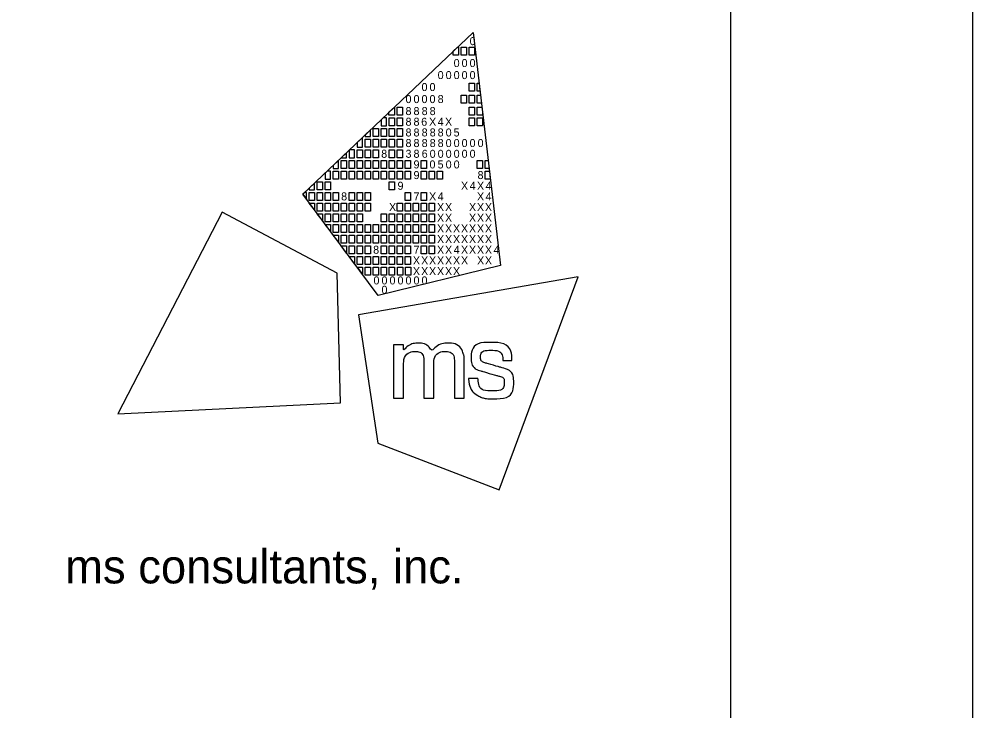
# Model space of a CAD drawing. Extents: x 0 to 34, y 0 to 22.
# Drawn here: x 32.032 to 34, y 2.686 to 4.114 of the extents above; entities that cross this region are included whole.
import ezdxf

# ---------------------------------------------------------------- set-up
doc = ezdxf.new("R2010")
doc.units = 0
for name, color, linetype in [('SH_Border', 7, 'Continuous'), ('SH_Cut_Line', 7, 'Continuous'), ('SH_Data', 7, 'Continuous')]:
    doc.layers.add(name, color=color, linetype=linetype)

msp = doc.modelspace()

# ---------------------------------------------------------------- linework, layer by layer
at = {"layer": 'SH_Border'}
for p, q in [((32.6175, 3.7519), (32.9688, 4.0861)), ((32.9688, 4.0861), (32.9688, 4.0861)), ((32.9688, 4.0861), (33.0253, 3.6052)), ((32.773, 3.543), (32.6175, 3.7519)), ((33.0253, 3.6052), (32.773, 3.543))]:
    msp.add_line(p, q, dxfattribs=at)
for points in [[(1.5, 21.5), (33.5, 21.5), (33.5, 0.5), (1.5, 0.5)], [(32.9279, 4.0472), (32.9369, 4.0558), (32.9389, 4.0558), (32.9389, 4.0393), (32.9279, 4.0393)], [(32.9444, 4.0558), (32.9554, 4.0558), (32.9554, 4.0393), (32.9444, 4.0393)], [(32.9609, 4.0558), (32.9719, 4.0558), (32.9719, 4.0393), (32.9609, 4.0393)], [(32.9606, 3.9815), (32.9716, 3.9815), (32.9716, 3.965), (32.9606, 3.965)], [(32.9771, 3.9815), (32.9811, 3.9815), (32.983, 3.965), (32.9771, 3.965)], [(32.9441, 3.9567), (32.9551, 3.9567), (32.9551, 3.9402), (32.9441, 3.9402)], [(32.9606, 3.9567), (32.9716, 3.9567), (32.9716, 3.9402), (32.9606, 3.9402)], [(32.9771, 3.9567), (32.984, 3.9567), (32.9859, 3.9402), (32.9771, 3.9402)], [(32.7953, 3.9211), (32.8064, 3.9316), (32.8064, 3.9154), (32.7953, 3.9154)], [(32.8123, 3.9319), (32.8233, 3.9319), (32.8233, 3.9154), (32.8123, 3.9154)], [(32.9606, 3.9319), (32.9716, 3.9319), (32.9716, 3.9154), (32.9606, 3.9154)], [(32.9771, 3.9319), (32.9869, 3.9319), (32.9881, 3.9218), (32.9881, 3.9154), (32.9771, 3.9154)], [(32.7958, 3.9099), (32.8068, 3.9099), (32.8068, 3.8934), (32.7958, 3.8934)], [(32.8123, 3.9099), (32.8233, 3.9099), (32.8233, 3.8934), (32.8123, 3.8934)], [(32.9606, 3.9099), (32.9716, 3.9099), (32.9716, 3.8934), (32.9606, 3.8934)], [(32.9771, 3.9099), (32.9881, 3.9099), (32.9881, 3.8934), (32.9771, 3.8934)], [(32.7627, 3.8879), (32.7737, 3.8879), (32.7737, 3.8714), (32.7627, 3.8714)], [(32.7793, 3.8879), (32.7903, 3.8879), (32.7903, 3.8714), (32.7793, 3.8714)], [(32.7958, 3.8879), (32.8068, 3.8879), (32.8068, 3.8714), (32.7958, 3.8714)], [(32.8123, 3.8879), (32.8233, 3.8879), (32.8233, 3.8714), (32.8123, 3.8714)], [(32.7462, 3.8659), (32.7572, 3.8659), (32.7572, 3.8494), (32.7462, 3.8494)], [(32.7627, 3.8659), (32.7737, 3.8659), (32.7737, 3.8494), (32.7627, 3.8494)], [(32.7793, 3.8659), (32.7903, 3.8659), (32.7903, 3.8494), (32.7793, 3.8494)], [(32.7958, 3.8659), (32.8068, 3.8659), (32.8068, 3.8494), (32.7958, 3.8494)], [(32.8123, 3.8659), (32.8233, 3.8659), (32.8233, 3.8494), (32.8123, 3.8494)], [(32.7297, 3.8439), (32.7407, 3.8439), (32.7407, 3.8273), (32.7297, 3.8273)], [(32.7462, 3.8439), (32.7572, 3.8439), (32.7572, 3.8273), (32.7462, 3.8273)], [(32.7627, 3.8439), (32.7737, 3.8439), (32.7737, 3.8273), (32.7627, 3.8273)], [(32.7958, 3.8439), (32.8068, 3.8439), (32.8068, 3.8273), (32.7958, 3.8273)], [(32.8123, 3.8439), (32.8233, 3.8439), (32.8233, 3.8273), (32.8123, 3.8273)], [(32.6967, 3.8218), (32.7077, 3.8218), (32.7077, 3.8053), (32.6967, 3.8053)], [(32.7132, 3.8218), (32.7242, 3.8218), (32.7242, 3.8053), (32.7132, 3.8053)], [(32.7297, 3.8218), (32.7407, 3.8218), (32.7407, 3.8053), (32.7297, 3.8053)], [(32.7462, 3.8218), (32.7572, 3.8218), (32.7572, 3.8053), (32.7462, 3.8053)], [(32.7627, 3.8218), (32.7737, 3.8218), (32.7737, 3.8053), (32.7627, 3.8053)], [(32.7793, 3.8218), (32.7903, 3.8218), (32.7903, 3.8053), (32.7793, 3.8053)], [(32.7958, 3.8218), (32.8068, 3.8218), (32.8068, 3.8053), (32.7958, 3.8053)], [(32.8123, 3.8218), (32.8233, 3.8218), (32.8233, 3.8053), (32.8123, 3.8053)], [(32.8288, 3.8218), (32.8398, 3.8218), (32.8398, 3.8053), (32.8288, 3.8053)], [(32.8618, 3.8218), (32.8728, 3.8218), (32.8728, 3.8053), (32.8618, 3.8053)], [(32.9771, 3.8218), (32.9881, 3.8218), (32.9881, 3.8053), (32.9771, 3.8053)], [(32.9935, 3.8218), (32.9998, 3.8218), (33.0018, 3.8053), (32.9935, 3.8053)], [(32.6802, 3.7998), (32.6912, 3.7998), (32.6912, 3.7833), (32.6802, 3.7833)], [(32.6967, 3.7998), (32.7077, 3.7998), (32.7077, 3.7833), (32.6967, 3.7833)], [(32.7132, 3.7998), (32.7242, 3.7998), (32.7242, 3.7833), (32.7132, 3.7833)], [(32.7297, 3.7998), (32.7407, 3.7998), (32.7407, 3.7833), (32.7297, 3.7833)], [(32.7462, 3.7998), (32.7572, 3.7998), (32.7572, 3.7833), (32.7462, 3.7833)], [(32.7627, 3.7998), (32.7737, 3.7998), (32.7737, 3.7833), (32.7627, 3.7833)], [(32.7793, 3.7998), (32.7903, 3.7998), (32.7903, 3.7833), (32.7793, 3.7833)], [(32.7958, 3.7998), (32.8068, 3.7998), (32.8068, 3.7833), (32.7958, 3.7833)], [(32.8123, 3.7998), (32.8233, 3.7998), (32.8233, 3.7833), (32.8123, 3.7833)], [(32.8288, 3.7998), (32.8398, 3.7998), (32.8398, 3.7833), (32.8288, 3.7833)], [(32.8618, 3.7998), (32.8728, 3.7998), (32.8728, 3.7833), (32.8618, 3.7833)], [(32.8783, 3.7998), (32.8893, 3.7998), (32.8893, 3.7833), (32.8783, 3.7833)], [(32.8947, 3.7998), (32.9057, 3.7998), (32.9057, 3.7833), (32.8947, 3.7833)], [(32.9935, 3.7998), (33.0024, 3.7998), (33.0044, 3.7833), (32.9935, 3.7833)], [(32.6471, 3.7778), (32.6581, 3.7778), (32.6581, 3.7613), (32.6471, 3.7613)], [(32.6637, 3.7778), (32.6747, 3.7778), (32.6747, 3.7613), (32.6637, 3.7613)], [(32.7958, 3.7778), (32.8068, 3.7778), (32.8068, 3.7613), (32.7958, 3.7613)], [(32.6306, 3.7558), (32.6416, 3.7558), (32.6416, 3.7393), (32.6306, 3.7393)], [(32.6471, 3.7558), (32.6581, 3.7558), (32.6581, 3.7393), (32.6471, 3.7393)], [(32.6637, 3.7558), (32.6747, 3.7558), (32.6747, 3.7393), (32.6637, 3.7393)], [(32.6802, 3.7558), (32.6912, 3.7558), (32.6912, 3.7393), (32.6802, 3.7393)], [(32.7132, 3.7558), (32.7242, 3.7558), (32.7242, 3.7393), (32.7132, 3.7393)], [(32.7297, 3.7558), (32.7407, 3.7558), (32.7407, 3.7393), (32.7297, 3.7393)], [(32.7462, 3.7558), (32.7572, 3.7558), (32.7572, 3.7393), (32.7462, 3.7393)], [(32.8288, 3.7558), (32.8398, 3.7558), (32.8398, 3.7393), (32.8288, 3.7393)], [(32.8618, 3.7558), (32.8728, 3.7558), (32.8728, 3.7393), (32.8618, 3.7393)], [(32.6306, 3.7338), (32.6416, 3.7338), (32.6416, 3.72)], [(32.6471, 3.7338), (32.6581, 3.7338), (32.6581, 3.7173), (32.6471, 3.7173)], [(32.6637, 3.7338), (32.6747, 3.7338), (32.6747, 3.7173), (32.6637, 3.7173)], [(32.6802, 3.7338), (32.6912, 3.7338), (32.6912, 3.7173), (32.6802, 3.7173)], [(32.6967, 3.7338), (32.7077, 3.7338), (32.7077, 3.7173), (32.6967, 3.7173)], [(32.7132, 3.7338), (32.7242, 3.7338), (32.7242, 3.7173), (32.7132, 3.7173)], [(32.7297, 3.7338), (32.7407, 3.7338), (32.7407, 3.7173), (32.7297, 3.7173)], [(32.7462, 3.7338), (32.7572, 3.7338), (32.7572, 3.7173), (32.7462, 3.7173)], [(32.8123, 3.7338), (32.8233, 3.7338), (32.8233, 3.7173), (32.8123, 3.7173)], [(32.8288, 3.7338), (32.8398, 3.7338), (32.8398, 3.7173), (32.8288, 3.7173)], [(32.8453, 3.7338), (32.8563, 3.7338), (32.8563, 3.7173), (32.8453, 3.7173)], [(32.8618, 3.7338), (32.8728, 3.7338), (32.8728, 3.7173), (32.8618, 3.7173)], [(32.8783, 3.7338), (32.8893, 3.7338), (32.8893, 3.7173), (32.8783, 3.7173)], [(32.6471, 3.7117), (32.6581, 3.7117), (32.6581, 3.698)], [(32.6637, 3.7117), (32.6747, 3.7117), (32.6747, 3.6952), (32.6637, 3.6952)], [(32.6802, 3.7117), (32.6912, 3.7117), (32.6912, 3.6952), (32.6802, 3.6952)], [(32.6967, 3.7117), (32.7077, 3.7117), (32.7077, 3.6952), (32.6967, 3.6952)], [(32.7132, 3.7117), (32.7242, 3.7117), (32.7242, 3.6952), (32.7132, 3.6952)], [(32.7297, 3.7117), (32.7407, 3.7117), (32.7407, 3.6952), (32.7297, 3.6952)], [(32.7793, 3.7117), (32.7903, 3.7117), (32.7903, 3.6952), (32.7793, 3.6952)], [(32.7958, 3.7117), (32.8068, 3.7117), (32.8068, 3.6952), (32.7958, 3.6952)], [(32.8123, 3.7117), (32.8233, 3.7117), (32.8233, 3.6952), (32.8123, 3.6952)], [(32.8288, 3.7117), (32.8398, 3.7117), (32.8398, 3.6952), (32.8288, 3.6952)], [(32.8453, 3.7117), (32.8563, 3.7117), (32.8563, 3.6952), (32.8453, 3.6952)], [(32.8618, 3.7117), (32.8728, 3.7117), (32.8728, 3.6952), (32.8618, 3.6952)], [(32.8783, 3.7117), (32.8893, 3.7117), (32.8893, 3.6952), (32.8783, 3.6952)], [(32.6637, 3.6897), (32.6747, 3.6897), (32.6747, 3.676)], [(32.6747, 3.6897), (32.6747, 3.6897), (32.6747, 3.6897)], [(32.6802, 3.6897), (32.6912, 3.6897), (32.6912, 3.6732), (32.6802, 3.6732)], [(32.6967, 3.6897), (32.7077, 3.6897), (32.7077, 3.6732), (32.6967, 3.6732)], [(32.7132, 3.6897), (32.7242, 3.6897), (32.7242, 3.6732), (32.7132, 3.6732)], [(32.7297, 3.6897), (32.7407, 3.6897), (32.7407, 3.6732), (32.7297, 3.6732)], [(32.7462, 3.6897), (32.7572, 3.6897), (32.7572, 3.6732), (32.7462, 3.6732)], [(32.7627, 3.6897), (32.7737, 3.6897), (32.7737, 3.6732), (32.7627, 3.6732)], [(32.7793, 3.6897), (32.7903, 3.6897), (32.7903, 3.6732), (32.7793, 3.6732)], [(32.7958, 3.6897), (32.8068, 3.6897), (32.8068, 3.6732), (32.7958, 3.6732)], [(32.8123, 3.6897), (32.8233, 3.6897), (32.8233, 3.6732), (32.8123, 3.6732)], [(32.8288, 3.6897), (32.8398, 3.6897), (32.8398, 3.6732), (32.8288, 3.6732)], [(32.8453, 3.6897), (32.8563, 3.6897), (32.8563, 3.6732), (32.8453, 3.6732)], [(32.8618, 3.6897), (32.8728, 3.6897), (32.8728, 3.6732), (32.8618, 3.6732)], [(32.8783, 3.6897), (32.8893, 3.6897), (32.8893, 3.6732), (32.8783, 3.6732)], [(32.6802, 3.6677), (32.6912, 3.6677), (32.6912, 3.654)], [(32.6967, 3.6677), (32.7077, 3.6677), (32.7077, 3.6512), (32.6967, 3.6512)], [(32.7132, 3.6677), (32.7242, 3.6677), (32.7242, 3.6512), (32.7132, 3.6512)], [(32.7297, 3.6677), (32.7407, 3.6677), (32.7407, 3.6512), (32.7297, 3.6512)], [(32.7462, 3.6677), (32.7572, 3.6677), (32.7572, 3.6512), (32.7462, 3.6512)], [(32.7627, 3.6677), (32.7737, 3.6677), (32.7737, 3.6512), (32.7627, 3.6512)], [(32.7793, 3.6677), (32.7903, 3.6677), (32.7903, 3.6512), (32.7793, 3.6512)], [(32.7958, 3.6677), (32.8068, 3.6677), (32.8068, 3.6512), (32.7958, 3.6512)], [(32.8123, 3.6677), (32.8233, 3.6677), (32.8233, 3.6512), (32.8123, 3.6512)], [(32.8288, 3.6677), (32.8398, 3.6677), (32.8398, 3.6512), (32.8288, 3.6512)], [(32.8453, 3.6677), (32.8563, 3.6677), (32.8563, 3.6512), (32.8453, 3.6512)], [(32.8618, 3.6677), (32.8728, 3.6677), (32.8728, 3.6512), (32.8618, 3.6512)], [(32.8783, 3.6677), (32.8893, 3.6677), (32.8893, 3.6512), (32.8783, 3.6512)], [(32.7077, 3.6305), (32.6965, 3.6457), (32.7077, 3.6457)], [(32.7132, 3.6457), (32.7242, 3.6457), (32.7242, 3.6292), (32.7132, 3.6292)], [(32.7297, 3.6457), (32.7407, 3.6457), (32.7407, 3.6292), (32.7297, 3.6292)], [(32.7462, 3.6457), (32.7572, 3.6457), (32.7572, 3.6292), (32.7462, 3.6292)], [(32.7793, 3.6457), (32.7903, 3.6457), (32.7903, 3.6292), (32.7793, 3.6292)], [(32.7958, 3.6457), (32.8068, 3.6457), (32.8068, 3.6292), (32.7958, 3.6292)], [(32.8123, 3.6457), (32.8233, 3.6457), (32.8233, 3.6292), (32.8123, 3.6292)], [(32.8288, 3.6457), (32.8398, 3.6457), (32.8398, 3.6292), (32.8288, 3.6292)], [(32.8618, 3.6457), (32.8728, 3.6457), (32.8728, 3.6292), (32.8618, 3.6292)], [(32.8783, 3.6457), (32.8893, 3.6457), (32.8893, 3.6292), (32.8783, 3.6292)], [(32.724, 3.6082), (32.7132, 3.6237), (32.7242, 3.6237)], [(32.7297, 3.6237), (32.7407, 3.6237), (32.7407, 3.6072), (32.7297, 3.6072)], [(32.7462, 3.6237), (32.7572, 3.6237), (32.7572, 3.6072), (32.7462, 3.6072)], [(32.7627, 3.6237), (32.7737, 3.6237), (32.7737, 3.6072), (32.7627, 3.6072)], [(32.7793, 3.6237), (32.7903, 3.6237), (32.7903, 3.6072), (32.7793, 3.6072)], [(32.7958, 3.6237), (32.8068, 3.6237), (32.8068, 3.6072), (32.7958, 3.6072)], [(32.8123, 3.6237), (32.8233, 3.6237), (32.8233, 3.6072), (32.8123, 3.6072)], [(32.8288, 3.6237), (32.8398, 3.6237), (32.8398, 3.6072), (32.8288, 3.6072)], [(32.7302, 3.6017), (32.7407, 3.6017), (32.7408, 3.5875)], [(32.7463, 3.6017), (32.7573, 3.6017), (32.7573, 3.5852), (32.7463, 3.5852)], [(32.763, 3.6017), (32.774, 3.6017), (32.774, 3.5852), (32.763, 3.5852)], [(32.7794, 3.6017), (32.7904, 3.6017), (32.7904, 3.5852), (32.7794, 3.5852)], [(32.796, 3.6017), (32.807, 3.6017), (32.807, 3.5852), (32.796, 3.5852)], [(32.8129, 3.6017), (32.8239, 3.6017), (32.8239, 3.5851), (32.8129, 3.5851)], [(32.8296, 3.6017), (32.8406, 3.6017), (32.8406, 3.5851), (32.8296, 3.5851)]]:
    msp.add_lwpolyline(points, close=True, dxfattribs=at)
for points in [[(32.7903, 3.9099), (32.7836, 3.9099), (32.7793, 3.9058), (32.7793, 3.8934), (32.7903, 3.8934), (32.7903, 3.9099)], [(32.7572, 3.8849), (32.7462, 3.8744), (32.7462, 3.8714), (32.7572, 3.8714), (32.7572, 3.8849)], [(32.7407, 3.8691), (32.7297, 3.8587), (32.7297, 3.8494), (32.7407, 3.8494), (32.7407, 3.8691)], [(32.7077, 3.8377), (32.6968, 3.8273), (32.7077, 3.8273), (32.7077, 3.8377)], [(32.7242, 3.8439), (32.7141, 3.8439), (32.7132, 3.843), (32.7132, 3.8273), (32.7242, 3.8273), (32.7242, 3.8439)], [(32.6912, 3.822), (32.6802, 3.8115), (32.6802, 3.8053), (32.6912, 3.8053), (32.6912, 3.822)], [(32.6747, 3.7998), (32.6679, 3.7998), (32.6637, 3.7958), (32.6637, 3.7833), (32.6747, 3.7833), (32.6747, 3.7998)], [(32.6416, 3.7749), (32.6306, 3.7644), (32.6306, 3.7613), (32.6416, 3.7613), (32.6416, 3.7749)], [(32.6251, 3.7558), (32.6216, 3.7558), (32.6175, 3.7519), (32.6251, 3.7417), (32.6251, 3.7558)], [(32.4512, 3.7149), (32.2359, 3.2988), (32.6956, 3.3215), (32.6884, 3.5892), (32.4512, 3.7149)], [(33.0229, 3.1422), (33.1859, 3.5814), (32.7324, 3.5029), (32.7722, 3.2381), (33.0229, 3.1422)]]:
    msp.add_lwpolyline(points, dxfattribs=at)
for points in [[(32.8048, 3.3315), (32.8048, 3.3315), (32.8048, 3.4409), (32.8048, 3.4409), (32.8048, 3.4409), (32.8255, 3.4409), (32.8255, 3.4409), (32.8255, 3.4409), (32.8255, 3.4297), (32.8255, 3.4297), (32.8346, 3.4399), (32.8457, 3.4445), (32.8555, 3.4445), (32.8688, 3.4445), (32.8791, 3.4372), (32.8837, 3.4266), (32.8915, 3.4381), (32.905, 3.4446), (32.9166, 3.4446), (32.9325, 3.4446), (32.9451, 3.435), (32.9494, 3.4213), (32.9494, 3.4212), (32.9494, 3.4212), (32.9494, 3.4212), (32.9501, 3.419), (32.9506, 3.4172), (32.9506, 3.4071), (32.9506, 3.4071), (32.9506, 3.3314), (32.9506, 3.3314), (32.9506, 3.3314), (32.9303, 3.3314), (32.9303, 3.3314), (32.9303, 3.3314), (32.9303, 3.4048), (32.9303, 3.4048), (32.9303, 3.4201), (32.9219, 3.4274), (32.911, 3.4274), (32.8995, 3.4274), (32.8879, 3.4171), (32.8879, 3.4001), (32.8879, 3.4001), (32.8879, 3.3315), (32.8879, 3.3315), (32.8879, 3.3315), (32.8674, 3.3315), (32.8674, 3.3315), (32.8674, 3.3315), (32.8674, 3.4059), (32.8674, 3.4059), (32.8674, 3.4203), (32.8588, 3.4274), (32.8496, 3.4274), (32.8384, 3.4274), (32.8254, 3.417), (32.8254, 3.3962), (32.8254, 3.3962), (32.8254, 3.3315), (32.8254, 3.3315), (32.8254, 3.3315), (32.8048, 3.3315), (32.8048, 3.3315)], [(32.9595, 3.3709), (32.9595, 3.3709), (32.9595, 3.3717), (32.9595, 3.3717), (32.9595, 3.3717), (32.9603, 3.3717), (32.9603, 3.3717), (32.9603, 3.3717), (32.9783, 3.3717), (32.9783, 3.3717), (32.9783, 3.3717), (32.9789, 3.3717), (32.9789, 3.3717), (32.9789, 3.3717), (32.979, 3.371), (32.979, 3.371), (32.9803, 3.3554), (32.9887, 3.346), (33.009, 3.346), (33.0273, 3.346), (33.0333, 3.3554), (33.0333, 3.3631), (33.0333, 3.3732), (33.0256, 3.3758), (33.0175, 3.378), (33.0175, 3.378), (32.987, 3.3867), (32.987, 3.3867), (32.972, 3.3909), (32.9648, 3.4019), (32.9648, 3.4142), (32.9648, 3.4303), (32.9768, 3.4462), (33.0052, 3.4462), (33.0348, 3.4462), (33.0489, 3.4285), (33.0489, 3.4095), (33.0489, 3.4095), (33.0489, 3.4087), (33.0489, 3.4087), (33.0489, 3.4087), (33.0482, 3.4087), (33.0482, 3.4087), (33.0482, 3.4087), (33.0312, 3.4087), (33.0312, 3.4087), (33.0312, 3.4087), (33.0305, 3.4087), (33.0305, 3.4087), (33.0305, 3.4087), (33.0305, 3.4094), (33.0305, 3.4094), (33.0301, 3.4208), (33.0226, 3.43), (33.0056, 3.43), (32.9891, 3.43), (32.9843, 3.4218), (32.9843, 3.4157), (32.9843, 3.4108), (32.9869, 3.4059), (32.9959, 3.4033), (32.9959, 3.4033), (33.0255, 3.3948), (33.0255, 3.3948), (33.0462, 3.3889), (33.0527, 3.3777), (33.0527, 3.3639), (33.0527, 3.3462), (33.041, 3.3298), (33.0087, 3.3298), (32.9952, 3.3298), (32.9877, 3.3321), (32.9823, 3.3348), (32.969, 3.3414), (32.9609, 3.3536), (32.9595, 3.3709)]]:
    msp.add_open_spline(points, degree=3, dxfattribs=at)
at = {"layer": 'SH_Cut_Line'}
msp.add_lwpolyline([(0, 0), (34, 0), (34, 22), (0, 22)], close=True, dxfattribs=at)
at = {"layer": 'SH_Data'}
msp.add_line((32.75, 3.5), (32.75, 3.5), dxfattribs=at)

# ---------------------------------------------------------------- texts
at = {"layer": 'SH_Border'}
for s, height, p in [('0', 0.0165, (32.9617, 4.0597)), ('0', 0.0165, (32.9288, 4.0145)), ('0', 0.0165, (32.9452, 4.0145)), ('0', 0.0165, (32.9617, 4.0145)), ('0', 0.0165, (32.8958, 3.9897)), ('0', 0.0165, (32.9123, 3.9897)), ('0', 0.0165, (32.9288, 3.9897)), ('0', 0.0165, (32.9452, 3.9897)), ('0', 0.0165, (32.9617, 3.9897)), ('0', 0.0165, (32.8625, 3.965)), ('0', 0.0165, (32.879, 3.965)), ('0', 0.0165, (32.8295, 3.9402)), ('0', 0.0165, (32.846, 3.9402)), ('0', 0.0165, (32.8625, 3.9402)), ('0', 0.0165, (32.879, 3.9402)), ('8', 0.0165, (32.8958, 3.9402)), ('8', 0.0165, (32.8295, 3.9154)), ('8', 0.0165, (32.846, 3.9154)), ('8', 0.0165, (32.8628, 3.9154)), ('8', 0.0165, (32.8793, 3.9154)), ('8', 0.0165, (32.8295, 3.8934)), ('8', 0.0165, (32.846, 3.8934)), ('6', 0.0165, (32.8618, 3.8934)), ('X', 0.0165, (32.8781, 3.8934)), ('4', 0.0165, (32.8958, 3.8934)), ('X', 0.0165, (32.911, 3.8934)), ('8', 0.0165, (32.8295, 3.8713)), ('8', 0.0165, (32.846, 3.8713)), ('8', 0.0165, (32.8628, 3.8713)), ('8', 0.0165, (32.8794, 3.8713)), ('8', 0.0165, (32.8958, 3.8713)), ('0', 0.0165, (32.9123, 3.8713)), ('5', 0.0165, (32.9287, 3.8713)), ('8', 0.0165, (32.8295, 3.8494)), ('8', 0.0165, (32.846, 3.8494)), ('8', 0.0165, (32.8628, 3.8494)), ('8', 0.0165, (32.8794, 3.8494)), ('8', 0.0165, (32.8958, 3.8494)), ('0', 0.0165, (32.9123, 3.8494)), ('0', 0.0165, (32.9288, 3.8494)), ('0', 0.0165, (32.9452, 3.8494)), ('0', 0.0165, (32.9617, 3.8494)), ('0', 0.0165, (32.9782, 3.8494)), ('8', 0.0165, (32.7793, 3.8273)), ('3', 0.0165, (32.8295, 3.8273)), ('8', 0.0165, (32.846, 3.8273)), ('6', 0.0165, (32.8629, 3.8273)), ('0', 0.0165, (32.8793, 3.8273)), ('0', 0.0165, (32.8958, 3.8273)), ('0', 0.0165, (32.9123, 3.8273)), ('0', 0.0165, (32.9288, 3.8273)), ('0', 0.0165, (32.9452, 3.8273)), ('0', 0.0165, (32.9617, 3.8273)), ('9', 0.0165, (32.846, 3.8053)), ('0', 0.0165, (32.879, 3.8053)), ('5', 0.0165, (32.8957, 3.8053)), ('0', 0.0165, (32.9123, 3.8053)), ('0', 0.0165, (32.9288, 3.8053)), ('9', 0.0165, (32.846, 3.7833)), ('8', 0.0165, (32.9781, 3.7833)), ('9', 0.0165, (32.813, 3.7613)), ('X', 0.0165, (32.9439, 3.7613)), ('4', 0.0165, (32.9617, 3.7613)), ('X', 0.0165, (32.9769, 3.7613)), ('4', 0.0165, (32.9946, 3.7613)), ('8', 0.0165, (32.6967, 3.7393)), ('7', 0.0165, (32.846, 3.7393)), ('X', 0.0165, (32.8781, 3.7393)), ('4', 0.0165, (32.8958, 3.7393)), ('X', 0.0165, (32.9769, 3.7393)), ('4', 0.0165, (32.9946, 3.7393)), ('X', 0.0165, (32.7955, 3.7173)), ('X', 0.0165, (32.8945, 3.7173)), ('X', 0.0165, (32.911, 3.7173)), ('X', 0.0165, (32.9604, 3.7173)), ('X', 0.0165, (32.9769, 3.7173)), ('X', 0.0165, (32.9933, 3.7173)), ('X', 0.0165, (32.8945, 3.6952)), ('X', 0.0165, (32.911, 3.6952)), ('X', 0.0165, (32.9604, 3.6952)), ('X', 0.0165, (32.9769, 3.6952)), ('X', 0.0165, (32.9933, 3.6952)), ('X', 0.0165, (32.8945, 3.6732)), ('X', 0.0165, (32.911, 3.6732)), ('X', 0.0165, (32.9274, 3.6732)), ('X', 0.0165, (32.9439, 3.6732)), ('X', 0.0165, (32.9604, 3.6732)), ('X', 0.0165, (32.9769, 3.6732)), ('X', 0.0165, (32.9933, 3.6732)), ('X', 0.0165, (32.8945, 3.6512)), ('X', 0.0165, (32.911, 3.6512)), ('X', 0.0165, (32.9274, 3.6512)), ('X', 0.0165, (32.9439, 3.6512)), ('X', 0.0165, (32.9604, 3.6512)), ('X', 0.0165, (32.9769, 3.6512)), ('X', 0.0165, (32.9933, 3.6512)), ('8', 0.0165, (32.7627, 3.6292)), ('7', 0.0165, (32.846, 3.6292)), ('X', 0.0165, (32.8945, 3.6292)), ('X', 0.0165, (32.911, 3.6292)), ('4', 0.0165, (32.9288, 3.6292)), ('X', 0.0165, (32.9439, 3.6292)), ('X', 0.0165, (32.9604, 3.6292)), ('X', 0.0165, (32.9769, 3.6292)), ('X', 0.0165, (32.9933, 3.6292)), ('4', 0.0165, (33.0111, 3.6292)), ('X', 0.0165, (32.8447, 3.6072)), ('X', 0.0165, (32.8616, 3.6072)), ('X', 0.0165, (32.878, 3.6072)), ('X', 0.0165, (32.8945, 3.6072)), ('X', 0.0165, (32.911, 3.6072)), ('X', 0.0165, (32.9274, 3.6072)), ('X', 0.0165, (32.9439, 3.6072)), ('X', 0.0165, (32.9771, 3.6072)), ('X', 0.0165, (32.9933, 3.6072)), ('X', 0.0165, (32.8447, 3.5851)), ('X', 0.0165, (32.8616, 3.5851)), ('X', 0.0165, (32.878, 3.5851)), ('X', 0.0165, (32.8945, 3.5851)), ('X', 0.0165, (32.911, 3.5851)), ('X', 0.0165, (32.9274, 3.5851)), ('0', 0.0165, (32.7634, 3.5659)), ('0', 0.0165, (32.7799, 3.5659)), ('0', 0.0165, (32.7965, 3.5659)), ('0', 0.0165, (32.813, 3.5659)), ('0', 0.0165, (32.8295, 3.5659)), ('0', 0.0165, (32.846, 3.5659)), ('0', 0.0165, (32.8625, 3.5659)), ('0', 0.0165, (32.7799, 3.5467)), ('ms consultants, inc.', 0.07, (32.1273, 2.9489))]:
    msp.add_text(s, height=height, rotation=360, dxfattribs=at).set_placement(p)

doc.saveas('drawing.dxf')
